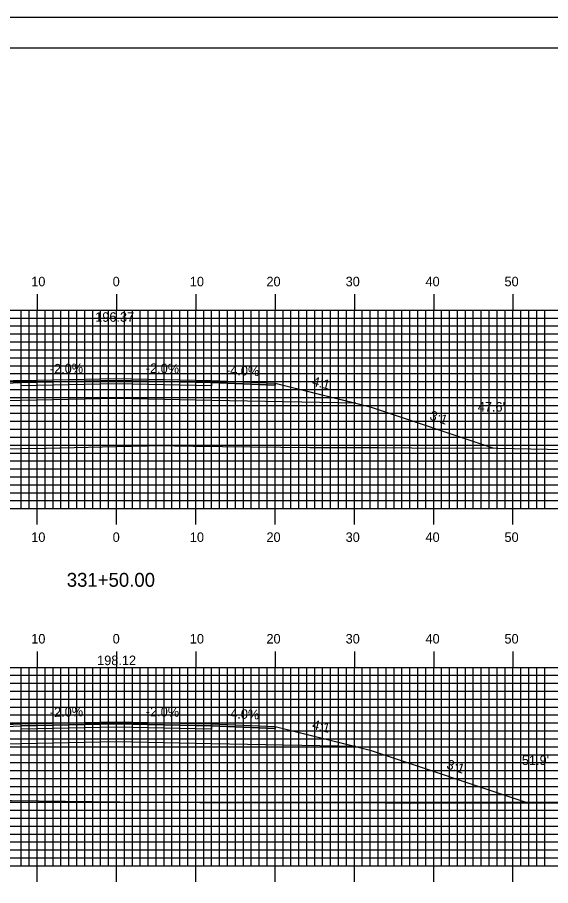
# Model space of a CAD drawing. Extents: x 1822392 to 1822735, y 442591 to 442811.
# Drawn here: x 1822545.3 to 1822612.5, y 442701.2 to 442810.5 of the extents above; entities that cross this region are included whole.
import ezdxf

# ---------------------------------------------------------------- set-up
doc = ezdxf.new("R2010")
doc.units = 0
for name, color, linetype in [('ANNOTATION', 7, 'Continuous'), ('BORDER', 7, 'Continuous'), ('D_Roadway_Centerline', 7, 'Continuous'), ('D_Roadway_Centerline_Text', 7, 'Continuous'), ('D_Roadway_Edge_Shoulder', 7, 'Continuous'), ('D_Roadway_Edge_TW', 7, 'Continuous'), ('D_Roadway_Pavement', 7, 'Continuous'), ('D_Roadway_SlopeLines', 7, 'Continuous'), ('D_Roadway_SubGrade', 7, 'Continuous'), ('D_Text_Standard', 7, 'Continuous'), ('H_V ANNOTATION', 7, 'Continuous'), ('MAJOR', 7, 'Continuous'), ('MINOR', 7, 'Continuous'), ('PLOT BOUNDARY', 7, 'Continuous'), ('S_Roadway_Centerline', 7, 'Continuous')]:
    doc.layers.add(name, color=color, linetype=linetype)

msp = doc.modelspace()

# ---------------------------------------------------------------- linework, layer by layer
at = {"layer": 'BORDER'}
msp.add_lwpolyline([(1822408.17, 442596.67), (1822728.17, 442596.67), (1822728.17, 442806.67), (1822408.17, 442806.67)], close=True, dxfattribs=at)
at = {"layer": 'D_Roadway_Centerline'}
for points in [[(1822508.73, 442755.8), (1822525.77, 442761.48), (1822527.6, 442761.94), (1822537.77, 442764.48), (1822545.77, 442764.8), (1822557.77, 442765.04), (1822569.77, 442764.8), (1822577.77, 442764.48), (1822587.94, 442761.94), (1822589.77, 442761.48), (1822605.37, 442756.28)], [(1822506.33, 442711.75), (1822525.77, 442718.23), (1822527.6, 442718.69), (1822537.77, 442721.23), (1822545.77, 442721.55), (1822557.77, 442721.79), (1822569.77, 442721.55), (1822577.77, 442721.23), (1822587.94, 442718.69), (1822589.77, 442718.23), (1822609.65, 442711.6)]]:
    msp.add_lwpolyline(points, dxfattribs=at)
at = {"layer": 'D_Roadway_Edge_Shoulder'}
for points in [[(1822545.77, 442764.8), (1822537.77, 442764.48), (1822537.77, 442764.23), (1822545.77, 442764.55)], [(1822569.77, 442764.8), (1822577.77, 442764.48), (1822577.77, 442764.23), (1822569.77, 442764.55)], [(1822545.77, 442721.55), (1822537.77, 442721.23), (1822537.77, 442720.98), (1822545.77, 442721.3)], [(1822569.77, 442721.55), (1822577.77, 442721.23), (1822577.77, 442720.98), (1822569.77, 442721.3)]]:
    msp.add_lwpolyline(points, close=True, dxfattribs=at)
at = {"layer": 'D_Roadway_Edge_TW'}
for points in [[(1822545.77, 442764.55), (1822545.77, 442764.8), (1822557.77, 442765.04), (1822569.77, 442764.8), (1822569.77, 442764.55), (1822557.77, 442764.79)], [(1822545.77, 442721.3), (1822545.77, 442721.55), (1822557.77, 442721.79), (1822569.77, 442721.55), (1822569.77, 442721.3), (1822557.77, 442721.54)]]:
    msp.add_lwpolyline(points, close=True, dxfattribs=at)
at = {"layer": 'D_Roadway_Pavement'}
for points in [[(1822545.77, 442764.13), (1822545.77, 442764.55), (1822557.77, 442764.79), (1822569.77, 442764.55), (1822569.77, 442764.13), (1822557.77, 442764.37)], [(1822545.77, 442720.88), (1822545.77, 442721.3), (1822557.77, 442721.54), (1822569.77, 442721.3), (1822569.77, 442720.88), (1822557.77, 442721.12)]]:
    msp.add_lwpolyline(points, close=True, dxfattribs=at)
at = {"layer": 'D_Roadway_SlopeLines'}
for points in [[(1822577.77, 442764.48), (1822589.77, 442761.48), (1822605.37, 442756.28)], [(1822577.77, 442721.23), (1822589.77, 442718.23), (1822609.65, 442711.6)]]:
    msp.add_lwpolyline(points, dxfattribs=at)
at = {"layer": 'D_Roadway_SubGrade'}
for points in [[(1822545.77, 442762.3), (1822527.6, 442761.94), (1822537.77, 442764.48), (1822537.77, 442764.23), (1822545.77, 442764.55), (1822557.77, 442764.79), (1822569.77, 442764.55), (1822577.77, 442764.23), (1822577.77, 442764.48), (1822587.94, 442761.94), (1822569.77, 442762.3), (1822557.77, 442762.54)], [(1822545.77, 442719.05), (1822527.6, 442718.69), (1822537.77, 442721.23), (1822537.77, 442720.98), (1822545.77, 442721.3), (1822557.77, 442721.54), (1822569.77, 442721.3), (1822577.77, 442720.98), (1822577.77, 442721.23), (1822587.94, 442718.69), (1822569.77, 442719.05), (1822557.77, 442719.29)]]:
    msp.add_lwpolyline(points, close=True, dxfattribs=at)
at = {"layer": 'MAJOR'}
for p, q in [((1822547.77, 442775.67), (1822547.77, 442773.67)), ((1822557.77, 442775.67), (1822557.77, 442773.67)), ((1822567.77, 442775.67), (1822567.77, 442773.67)), ((1822577.77, 442775.67), (1822577.77, 442773.67)), ((1822587.77, 442775.67), (1822587.77, 442773.67)), ((1822597.77, 442775.67), (1822597.77, 442773.67)), ((1822607.77, 442775.67), (1822607.77, 442773.67)), ((1822417.77, 442773.67), (1822697.77, 442773.67)), ((1822417.77, 442773.67), (1822697.77, 442773.67)), ((1822547.77, 442748.67), (1822547.77, 442773.67)), ((1822557.77, 442748.67), (1822557.77, 442773.67)), ((1822567.77, 442748.67), (1822567.77, 442773.67)), ((1822577.77, 442748.67), (1822577.77, 442773.67)), ((1822587.77, 442748.67), (1822587.77, 442773.67)), ((1822597.77, 442748.67), (1822597.77, 442773.67)), ((1822607.77, 442748.67), (1822607.77, 442773.67)), ((1822417.77, 442768.67), (1822697.77, 442768.67)), ((1822417.77, 442763.67), (1822697.77, 442763.67)), ((1822417.77, 442758.67), (1822697.77, 442758.67)), ((1822417.77, 442753.67), (1822697.77, 442753.67)), ((1822417.77, 442748.67), (1822697.77, 442748.67)), ((1822417.77, 442748.67), (1822697.77, 442748.67)), ((1822547.77, 442746.66), (1822547.77, 442748.67)), ((1822557.77, 442746.66), (1822557.77, 442748.67)), ((1822567.77, 442746.66), (1822567.77, 442748.67)), ((1822577.77, 442746.66), (1822577.77, 442748.67)), ((1822587.77, 442746.66), (1822587.77, 442748.67)), ((1822597.77, 442746.66), (1822597.77, 442748.67)), ((1822607.77, 442746.66), (1822607.77, 442748.67)), ((1822547.77, 442730.67), (1822547.77, 442728.67)), ((1822557.77, 442730.67), (1822557.77, 442728.67)), ((1822567.77, 442730.67), (1822567.77, 442728.67)), ((1822577.77, 442730.67), (1822577.77, 442728.67)), ((1822587.77, 442730.67), (1822587.77, 442728.67)), ((1822597.77, 442730.67), (1822597.77, 442728.67)), ((1822607.77, 442730.67), (1822607.77, 442728.67)), ((1822417.77, 442728.67), (1822697.77, 442728.67)), ((1822417.77, 442728.67), (1822697.77, 442728.67)), ((1822547.77, 442703.67), (1822547.77, 442728.67)), ((1822557.77, 442703.67), (1822557.77, 442728.67)), ((1822567.77, 442703.67), (1822567.77, 442728.67)), ((1822577.77, 442703.67), (1822577.77, 442728.67)), ((1822587.77, 442703.67), (1822587.77, 442728.67)), ((1822597.77, 442703.67), (1822597.77, 442728.67)), ((1822607.77, 442703.67), (1822607.77, 442728.67)), ((1822417.77, 442723.67), (1822697.77, 442723.67)), ((1822417.77, 442718.67), (1822697.77, 442718.67)), ((1822417.77, 442713.67), (1822697.77, 442713.67)), ((1822417.77, 442708.67), (1822697.77, 442708.67)), ((1822417.77, 442703.67), (1822697.77, 442703.67)), ((1822417.77, 442703.67), (1822697.77, 442703.67)), ((1822547.77, 442701.66), (1822547.77, 442703.67)), ((1822557.77, 442701.66), (1822557.77, 442703.67)), ((1822567.77, 442701.66), (1822567.77, 442703.67)), ((1822577.77, 442701.66), (1822577.77, 442703.67)), ((1822587.77, 442701.66), (1822587.77, 442703.67)), ((1822597.77, 442701.66), (1822597.77, 442703.67)), ((1822607.77, 442701.66), (1822607.77, 442703.67))]:
    msp.add_line(p, q, dxfattribs=at)
at = {"layer": 'MINOR'}
for p, q in [((1822545.77, 442748.67), (1822545.77, 442773.67)), ((1822546.77, 442748.67), (1822546.77, 442773.67)), ((1822548.77, 442748.67), (1822548.77, 442773.67)), ((1822549.77, 442748.67), (1822549.77, 442773.67)), ((1822550.77, 442748.67), (1822550.77, 442773.67)), ((1822551.77, 442748.67), (1822551.77, 442773.67)), ((1822552.77, 442748.67), (1822552.77, 442773.67)), ((1822553.77, 442748.67), (1822553.77, 442773.67)), ((1822554.77, 442748.67), (1822554.77, 442773.67)), ((1822555.77, 442748.67), (1822555.77, 442773.67)), ((1822556.77, 442748.67), (1822556.77, 442773.67)), ((1822558.77, 442748.67), (1822558.77, 442773.67)), ((1822559.77, 442748.67), (1822559.77, 442773.67)), ((1822560.77, 442748.67), (1822560.77, 442773.67)), ((1822561.77, 442748.67), (1822561.77, 442773.67)), ((1822562.77, 442748.67), (1822562.77, 442773.67)), ((1822563.77, 442748.67), (1822563.77, 442773.67)), ((1822564.77, 442748.67), (1822564.77, 442773.67)), ((1822565.77, 442748.67), (1822565.77, 442773.67)), ((1822566.77, 442748.67), (1822566.77, 442773.67)), ((1822568.77, 442748.67), (1822568.77, 442773.67)), ((1822569.77, 442748.67), (1822569.77, 442773.67)), ((1822570.77, 442748.67), (1822570.77, 442773.67)), ((1822571.77, 442748.67), (1822571.77, 442773.67)), ((1822572.77, 442748.67), (1822572.77, 442773.67)), ((1822573.77, 442748.67), (1822573.77, 442773.67)), ((1822574.77, 442748.67), (1822574.77, 442773.67)), ((1822575.77, 442748.67), (1822575.77, 442773.67)), ((1822576.77, 442748.67), (1822576.77, 442773.67)), ((1822578.77, 442748.67), (1822578.77, 442773.67)), ((1822579.77, 442748.67), (1822579.77, 442773.67)), ((1822580.77, 442748.67), (1822580.77, 442773.67)), ((1822581.77, 442748.67), (1822581.77, 442773.67)), ((1822582.77, 442748.67), (1822582.77, 442773.67)), ((1822583.77, 442748.67), (1822583.77, 442773.67)), ((1822584.77, 442748.67), (1822584.77, 442773.67)), ((1822585.77, 442748.67), (1822585.77, 442773.67)), ((1822586.77, 442748.67), (1822586.77, 442773.67)), ((1822588.77, 442748.67), (1822588.77, 442773.67)), ((1822589.77, 442748.67), (1822589.77, 442773.67)), ((1822590.77, 442748.67), (1822590.77, 442773.67)), ((1822591.77, 442748.67), (1822591.77, 442773.67)), ((1822592.77, 442748.67), (1822592.77, 442773.67)), ((1822593.77, 442748.67), (1822593.77, 442773.67)), ((1822594.77, 442748.67), (1822594.77, 442773.67)), ((1822595.77, 442748.67), (1822595.77, 442773.67)), ((1822596.77, 442748.67), (1822596.77, 442773.67)), ((1822598.77, 442748.67), (1822598.77, 442773.67)), ((1822599.77, 442748.67), (1822599.77, 442773.67)), ((1822600.77, 442748.67), (1822600.77, 442773.67)), ((1822601.77, 442748.67), (1822601.77, 442773.67)), ((1822602.77, 442748.67), (1822602.77, 442773.67)), ((1822603.77, 442748.67), (1822603.77, 442773.67)), ((1822604.77, 442748.67), (1822604.77, 442773.67)), ((1822605.77, 442748.67), (1822605.77, 442773.67)), ((1822606.77, 442748.67), (1822606.77, 442773.67)), ((1822608.77, 442748.67), (1822608.77, 442773.67)), ((1822609.77, 442748.67), (1822609.77, 442773.67)), ((1822610.77, 442748.67), (1822610.77, 442773.67)), ((1822611.77, 442748.67), (1822611.77, 442773.67)), ((1822417.77, 442772.67), (1822697.77, 442772.67)), ((1822417.77, 442771.67), (1822697.77, 442771.67)), ((1822417.77, 442770.67), (1822697.77, 442770.67)), ((1822417.77, 442769.67), (1822697.77, 442769.67)), ((1822417.77, 442767.67), (1822697.77, 442767.67)), ((1822417.77, 442766.67), (1822697.77, 442766.67)), ((1822417.77, 442765.67), (1822697.77, 442765.67)), ((1822417.77, 442764.67), (1822697.77, 442764.67)), ((1822417.77, 442762.67), (1822697.77, 442762.67)), ((1822417.77, 442761.67), (1822697.77, 442761.67)), ((1822417.77, 442760.67), (1822697.77, 442760.67)), ((1822417.77, 442759.67), (1822697.77, 442759.67)), ((1822417.77, 442757.67), (1822697.77, 442757.67)), ((1822417.77, 442756.67), (1822697.77, 442756.67)), ((1822417.77, 442755.67), (1822697.77, 442755.67)), ((1822417.77, 442754.67), (1822697.77, 442754.67)), ((1822417.77, 442752.67), (1822697.77, 442752.67)), ((1822417.77, 442751.67), (1822697.77, 442751.67)), ((1822417.77, 442750.67), (1822697.77, 442750.67)), ((1822417.77, 442749.67), (1822697.77, 442749.67)), ((1822545.77, 442703.67), (1822545.77, 442728.67)), ((1822546.77, 442703.67), (1822546.77, 442728.67)), ((1822548.77, 442703.67), (1822548.77, 442728.67)), ((1822549.77, 442703.67), (1822549.77, 442728.67)), ((1822550.77, 442703.67), (1822550.77, 442728.67)), ((1822551.77, 442703.67), (1822551.77, 442728.67)), ((1822552.77, 442703.67), (1822552.77, 442728.67)), ((1822553.77, 442703.67), (1822553.77, 442728.67)), ((1822554.77, 442703.67), (1822554.77, 442728.67)), ((1822555.77, 442703.67), (1822555.77, 442728.67)), ((1822556.77, 442703.67), (1822556.77, 442728.67)), ((1822558.77, 442703.67), (1822558.77, 442728.67)), ((1822559.77, 442703.67), (1822559.77, 442728.67)), ((1822560.77, 442703.67), (1822560.77, 442728.67)), ((1822561.77, 442703.67), (1822561.77, 442728.67)), ((1822562.77, 442703.67), (1822562.77, 442728.67)), ((1822563.77, 442703.67), (1822563.77, 442728.67)), ((1822564.77, 442703.67), (1822564.77, 442728.67)), ((1822565.77, 442703.67), (1822565.77, 442728.67)), ((1822566.77, 442703.67), (1822566.77, 442728.67)), ((1822568.77, 442703.67), (1822568.77, 442728.67)), ((1822569.77, 442703.67), (1822569.77, 442728.67)), ((1822570.77, 442703.67), (1822570.77, 442728.67)), ((1822571.77, 442703.67), (1822571.77, 442728.67)), ((1822572.77, 442703.67), (1822572.77, 442728.67)), ((1822573.77, 442703.67), (1822573.77, 442728.67)), ((1822574.77, 442703.67), (1822574.77, 442728.67)), ((1822575.77, 442703.67), (1822575.77, 442728.67)), ((1822576.77, 442703.67), (1822576.77, 442728.67)), ((1822578.77, 442703.67), (1822578.77, 442728.67)), ((1822579.77, 442703.67), (1822579.77, 442728.67)), ((1822580.77, 442703.67), (1822580.77, 442728.67)), ((1822581.77, 442703.67), (1822581.77, 442728.67)), ((1822582.77, 442703.67), (1822582.77, 442728.67)), ((1822583.77, 442703.67), (1822583.77, 442728.67)), ((1822584.77, 442703.67), (1822584.77, 442728.67)), ((1822585.77, 442703.67), (1822585.77, 442728.67)), ((1822586.77, 442703.67), (1822586.77, 442728.67)), ((1822588.77, 442703.67), (1822588.77, 442728.67)), ((1822589.77, 442703.67), (1822589.77, 442728.67)), ((1822590.77, 442703.67), (1822590.77, 442728.67)), ((1822591.77, 442703.67), (1822591.77, 442728.67)), ((1822592.77, 442703.67), (1822592.77, 442728.67)), ((1822593.77, 442703.67), (1822593.77, 442728.67)), ((1822594.77, 442703.67), (1822594.77, 442728.67)), ((1822595.77, 442703.67), (1822595.77, 442728.67)), ((1822596.77, 442703.67), (1822596.77, 442728.67)), ((1822598.77, 442703.67), (1822598.77, 442728.67)), ((1822599.77, 442703.67), (1822599.77, 442728.67)), ((1822600.77, 442703.67), (1822600.77, 442728.67)), ((1822601.77, 442703.67), (1822601.77, 442728.67)), ((1822602.77, 442703.67), (1822602.77, 442728.67)), ((1822603.77, 442703.67), (1822603.77, 442728.67)), ((1822604.77, 442703.67), (1822604.77, 442728.67)), ((1822605.77, 442703.67), (1822605.77, 442728.67)), ((1822606.77, 442703.67), (1822606.77, 442728.67)), ((1822608.77, 442703.67), (1822608.77, 442728.67)), ((1822609.77, 442703.67), (1822609.77, 442728.67)), ((1822610.77, 442703.67), (1822610.77, 442728.67)), ((1822611.77, 442703.67), (1822611.77, 442728.67)), ((1822417.77, 442727.67), (1822697.77, 442727.67)), ((1822417.77, 442726.67), (1822697.77, 442726.67)), ((1822417.77, 442725.67), (1822697.77, 442725.67)), ((1822417.77, 442724.67), (1822697.77, 442724.67)), ((1822417.77, 442722.67), (1822697.77, 442722.67)), ((1822417.77, 442721.67), (1822697.77, 442721.67)), ((1822417.77, 442720.67), (1822697.77, 442720.67)), ((1822417.77, 442719.67), (1822697.77, 442719.67)), ((1822417.77, 442717.67), (1822697.77, 442717.67)), ((1822417.77, 442716.67), (1822697.77, 442716.67)), ((1822417.77, 442715.67), (1822697.77, 442715.67)), ((1822417.77, 442714.67), (1822697.77, 442714.67)), ((1822417.77, 442712.67), (1822697.77, 442712.67)), ((1822417.77, 442711.67), (1822697.77, 442711.67)), ((1822417.77, 442710.67), (1822697.77, 442710.67)), ((1822417.77, 442709.67), (1822697.77, 442709.67)), ((1822417.77, 442707.67), (1822697.77, 442707.67)), ((1822417.77, 442706.67), (1822697.77, 442706.67)), ((1822417.77, 442705.67), (1822697.77, 442705.67)), ((1822417.77, 442704.67), (1822697.77, 442704.67))]:
    msp.add_line(p, q, dxfattribs=at)
at = {"layer": 'PLOT BOUNDARY'}
msp.add_lwpolyline([(1822391.98, 442590.55), (1822731.98, 442590.55), (1822731.98, 442810.55), (1822391.98, 442810.55)], close=True, dxfattribs=at)
at = {"layer": 'S_Roadway_Centerline'}
for points in [[(1822497.4, 442755.69), (1822499.43, 442755.66), (1822523.29, 442756.01), (1822530.91, 442756.15), (1822545.83, 442756.25), (1822548.9, 442756.28), (1822550.61, 442756.31), (1822557.81, 442756.47), (1822563.81, 442756.6), (1822565.09, 442756.56), (1822567.47, 442756.54), (1822582.16, 442756.38), (1822590.83, 442756.38), (1822599.22, 442756.28), (1822603.75, 442756.31), (1822616.29, 442756.06)], [(1822498.65, 442711.71), (1822510.54, 442711.77), (1822511.96, 442711.81), (1822521.66, 442711.9), (1822527.19, 442711.81), (1822534.45, 442711.91), (1822544.54, 442711.9), (1822561.61, 442711.7), (1822561.66, 442711.7), (1822561.69, 442711.7), (1822561.82, 442711.7), (1822574.76, 442711.61), (1822578.21, 442711.64), (1822588.42, 442711.63), (1822594.9, 442711.55), (1822606.95, 442711.61), (1822611.99, 442711.6), (1822626.12, 442711.58)]]:
    msp.add_lwpolyline(points, dxfattribs=at)

# ---------------------------------------------------------------- texts
at = {"layer": 'ANNOTATION'}
for s, rotation, p in [('-2.0%', 1.1458, (1822549.38, 442765.67)), ('-2.0%', 358.8542, (1822561.46, 442765.77)), ('-4.0%', 357.7094, (1822571.56, 442765.53)), ('4:1', 345.9638, (1822582.36, 442764.19)), ('3:1', 341.5652, (1822597.17, 442759.92)), ('-2.0%', 1.1458, (1822549.38, 442722.42)), ('-2.0%', 358.8542, (1822561.46, 442722.52)), ('-4.0%', 357.7094, (1822571.56, 442722.28)), ('4:1', 345.9638, (1822582.36, 442720.94)), ('3:1', 341.5652, (1822599.31, 442715.96))]:
    msp.add_text(s, height=1.2, rotation=rotation, dxfattribs=at).set_placement(p)
at = {"layer": 'D_Roadway_Centerline'}
for s, p in [('C', (1822557.76, 442765.04)), ('L', (1822557.77, 442765.03)), ('C', (1822557.76, 442721.79)), ('L', (1822557.77, 442721.78))]:
    msp.add_text(s, height=0.0146, dxfattribs=at).set_placement(p)
at = {"layer": 'D_Roadway_Centerline_Text'}
for s, p in [('196.37', (1822555.09, 442772.2)), ('198.12', (1822555.33, 442728.95))]:
    msp.add_text(s, height=1.2, dxfattribs=at).set_placement(p)
at = {"layer": 'D_Text_Standard'}
for s, p in [("47.6'", (1822603.33, 442760.88)), ("51.9'", (1822608.89, 442716.37))]:
    msp.add_text(s, height=1.2, dxfattribs=at).set_placement(p)
at = {"layer": 'H_V ANNOTATION'}
for s, height, p in [('10', 1.2, (1822547.02, 442776.67)), ('0', 1.2, (1822557.29, 442776.67)), ('10', 1.2, (1822567.02, 442776.67)), ('20', 1.2, (1822576.68, 442776.67)), ('30', 1.2, (1822586.67, 442776.67)), ('40', 1.2, (1822596.74, 442776.67)), ('50', 1.2, (1822606.7, 442776.67)), ('10', 1.2, (1822547.02, 442744.47)), ('0', 1.2, (1822557.29, 442744.47)), ('10', 1.2, (1822567.02, 442744.47)), ('20', 1.2, (1822576.68, 442744.47)), ('30', 1.2, (1822586.67, 442744.47)), ('40', 1.2, (1822596.74, 442744.47)), ('50', 1.2, (1822606.7, 442744.47)), ('331+50.00', 1.75, (1822551.5, 442738.82)), ('10', 1.2, (1822547.02, 442731.67)), ('0', 1.2, (1822557.29, 442731.67)), ('10', 1.2, (1822567.02, 442731.67)), ('20', 1.2, (1822576.68, 442731.67)), ('30', 1.2, (1822586.67, 442731.67)), ('40', 1.2, (1822596.74, 442731.67)), ('50', 1.2, (1822606.7, 442731.67))]:
    msp.add_text(s, height=height, dxfattribs=at).set_placement(p)

doc.saveas('drawing.dxf')
